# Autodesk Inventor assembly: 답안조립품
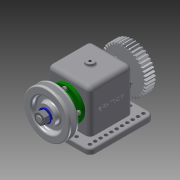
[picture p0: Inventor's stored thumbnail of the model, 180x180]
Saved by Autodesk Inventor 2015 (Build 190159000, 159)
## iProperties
Created: 2018-11
Part Number: 답안조립품
Document SubType Name: Assembly
Designer: now
Author: now
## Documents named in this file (13)
- C:\Users\now\Desktop\481108V1009\답안조립품.iam
- C:\Users\now\Desktop\481108V1009\V벨트풀리.ipt
- C:\Users\now\Desktop\481108V1009\너트 M12x1.25.ipt
- C:\Users\now\Desktop\481108V1009\베어링 6203.ipt
- C:\Users\now\Desktop\481108V1009\본체.ipt
- C:\Users\now\Desktop\481108V1009\볼트 M4.ipt
- C:\Users\now\Desktop\481108V1009\부시.ipt
- C:\Users\now\Desktop\481108V1009\스퍼기어.ipt
- C:\Users\now\Desktop\481108V1009\오일 실 26 38 8.ipt
- C:\Users\now\Desktop\481108V1009\와셔 12x24.ipt
- C:\Users\now\Desktop\481108V1009\축.ipt
- C:\Users\now\Desktop\481108V1009\커버.ipt
- C:\Users\now\Desktop\481108V1009\키 5x5x12.ipt
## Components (1 placed, 1 different names)
1. V벨트풀리:1 — 각도:4
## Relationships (1: Angle 1)
- 각도:4 [Angle]: V벨트풀리:1
